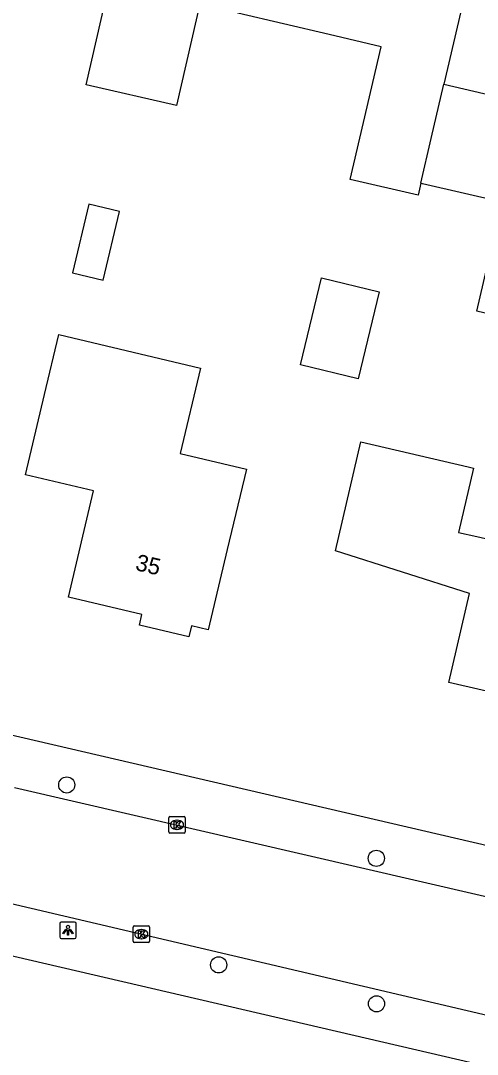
# Model space of a CAD drawing. Extents: x 162186 to 163152, y 385513 to 386513.
# Drawn here: x 162714.9 to 162742.5, y 385892.3 to 385954.9 of the extents above; entities that cross this region are included whole.
import ezdxf

# ---------------------------------------------------------------- set-up
doc = ezdxf.new("R2010")
doc.units = 0
for name, color, linetype in [('IMGEO_Boom', 7, 'Continuous'), ('IMGEO_Kolk', 7, 'Continuous'), ('IMGEO_Lichtpunt', 7, 'Continuous'), ('IMGEO_Pand', 7, 'Continuous'), ('IMGEO_Pand_nummerreeks', 7, 'Continuous'), ('IMGEO_Rijbaan_lokaal_open', 7, 'Continuous'), ('IMGEO_Voetpad_open', 7, 'Continuous')]:
    doc.layers.add(name, color=color, linetype=linetype)

msp = doc.modelspace()

# ---------------------------------------------------------------- linework, layer by layer
at = {"layer": 'IMGEO_Boom'}
for centre in [(162717.658, 385908.645), (162736.394, 385904.2), (162726.851, 385897.749), (162736.406, 385895.394)]:
    msp.add_circle(centre, 0.489, dxfattribs=at)
at = {"layer": 'IMGEO_Kolk'}
for p, q in [((162723.829, 385905.805), (162723.829, 385906.657)), ((162723.904, 385906.731), (162724.756, 385906.731)), ((162724.317, 385906.511), (162724.342, 385906.511)), ((162724.83, 385906.657), (162724.83, 385905.805)), ((162724.756, 385905.731), (162723.904, 385905.731)), ((162724.34, 385905.951), (162724.315, 385905.951)), ((162721.672, 385899.185), (162721.672, 385900.037)), ((162721.747, 385900.111), (162722.599, 385900.111)), ((162722.673, 385900.037), (162722.673, 385899.185)), ((162722.16, 385899.891), (162722.185, 385899.891)), ((162722.599, 385899.111), (162721.747, 385899.111)), ((162722.183, 385899.331), (162722.158, 385899.331))]:
    msp.add_line(p, q, dxfattribs=at)
for points in [[(162723.829, 385905.805), (162723.829, 385906.657)], [(162723.904, 385906.731), (162724.756, 385906.731)], [(162724.15, 385906.431), (162724.273, 385906.431), (162724.273, 385906.28), (162724.403, 385906.431), (162724.567, 385906.431), (162724.421, 385906.28), (162724.574, 385906.031), (162724.422, 385906.031), (162724.337, 385906.195), (162724.273, 385906.128), (162724.273, 385906.031), (162724.15, 385906.031), (162724.15, 385906.431)], [(162724.83, 385906.657), (162724.83, 385905.805)], [(162724.756, 385905.731), (162723.904, 385905.731)], [(162721.672, 385899.185), (162721.672, 385900.037)], [(162721.747, 385900.111), (162722.599, 385900.111)], [(162722.673, 385900.037), (162722.673, 385899.185)], [(162721.993, 385899.811), (162722.116, 385899.811), (162722.116, 385899.66), (162722.246, 385899.811), (162722.41, 385899.811), (162722.264, 385899.66), (162722.417, 385899.411), (162722.265, 385899.411), (162722.18, 385899.575), (162722.116, 385899.508), (162722.116, 385899.411), (162721.993, 385899.411), (162721.993, 385899.811)], [(162722.599, 385899.111), (162721.747, 385899.111)]]:
    msp.add_lwpolyline(points, dxfattribs=at)
for centre, start, end in [((162723.906, 385906.655), 91.55205, 178.44795), ((162723.906, 385906.655), 91.55205, 178.44795), ((162724.754, 385906.655), 1.55205, 88.44795), ((162724.754, 385906.655), 1.55205, 88.44795), ((162723.906, 385905.807), 181.55205, 268.44795), ((162723.906, 385905.807), 181.55205, 268.44795), ((162724.754, 385905.807), 271.55205, 358.44795), ((162724.754, 385905.807), 271.55205, 358.44795), ((162721.749, 385900.035), 91.55205, 178.44795), ((162721.749, 385900.035), 91.55205, 178.44795), ((162722.597, 385900.035), 1.55205, 88.44795), ((162722.597, 385900.035), 1.55205, 88.44795), ((162721.749, 385899.187), 181.55205, 268.44795), ((162721.749, 385899.187), 181.55205, 268.44795), ((162722.597, 385899.187), 271.55205, 358.44795), ((162722.597, 385899.187), 271.55205, 358.44795)]:
    msp.add_arc(centre, 0.0765, start, end, dxfattribs=at)
for centre, major_axis, ratio, start_param, end_param in [((162724.316, 385906.231), (-0.387, 0.002), 0.722429, 4.712389, 7.853982), ((162724.341, 385906.231), (-0.39, 0.002), 0.717154, 1.570796, 4.712389), ((162722.159, 385899.611), (-0.387, 0.002), 0.722429, 4.712389, 7.853982), ((162722.184, 385899.611), (-0.39, 0.002), 0.717154, 1.570796, 4.712389)]:
    msp.add_ellipse(centre, major_axis=major_axis, ratio=ratio, start_param=start_param, end_param=end_param, dxfattribs=at)
at = {"layer": 'IMGEO_Lichtpunt'}
for p, q in [((162717.234, 385900.249), (162717.234, 385899.442)), ((162717.234, 385900.249), (162717.234, 385899.442)), ((162718.136, 385900.344), (162717.328, 385900.344)), ((162718.136, 385900.344), (162717.328, 385900.344)), ((162718.23, 385899.442), (162718.23, 385900.249)), ((162718.23, 385899.442), (162718.23, 385900.249)), ((162717.328, 385899.348), (162718.136, 385899.348)), ((162717.328, 385899.348), (162718.136, 385899.348))]:
    msp.add_line(p, q, dxfattribs=at)
for points in [[(162717.608, 385899.913), (162717.647, 385899.885), (162717.459, 385899.623), (162717.421, 385899.65), (162717.608, 385899.913)], [(162717.71, 385899.865), (162717.757, 385899.865), (162717.757, 385899.543), (162717.71, 385899.543), (162717.71, 385899.865)], [(162717.82, 385899.885), (162717.858, 385899.912), (162718.045, 385899.65), (162718.006, 385899.622), (162717.82, 385899.885)]]:
    msp.add_lwpolyline(points, dxfattribs=at)
msp.add_circle((162717.733, 385900.047), 0.0994, dxfattribs=at)
for centre, start, end in [((162717.328, 385900.249), 90, 180), ((162717.328, 385900.249), 90, 180), ((162718.136, 385900.249), 0, 90), ((162718.136, 385900.249), 0, 90), ((162717.328, 385899.442), 180, 270), ((162717.328, 385899.442), 180, 270), ((162718.136, 385899.442), 270, 0), ((162718.136, 385899.442), 270, 360)]:
    msp.add_arc(centre, 0.0946, start, end, dxfattribs=at)
at = {"layer": 'IMGEO_Pand'}
for points in [[(162710.429, 385963.844), (162711.409, 385968.122), (162712.525, 385972.995), (162723.764, 385970.421), (162723.08, 385967.436), (162728.081, 385966.291), (162726.965, 385961.418), (162724.3, 385949.784), (162718.826, 385951.037), (162720.076, 385956.496), (162716.818, 385957.242), (162717.936, 385962.125), (162710.429, 385963.844)], [(162739.083, 385945.073), (162738.915, 385944.35), (162734.815, 385945.303), (162735.615, 385948.744), (162736.683, 385953.34), (162733.539, 385954.078), (162728.021, 385955.374), (162728.897, 385959.103), (162730.143, 385958.81), (162730.403, 385959.915), (162731.546, 385964.782), (162730.747, 385964.968), (162730.937, 385965.787), (162731.101, 385965.749), (162731.865, 385969.034), (162736.847, 385967.875), (162736.729, 385967.37), (162739.924, 385966.627), (162738.351, 385959.864), (162742.304, 385958.944), (162740.473, 385951.068)], [(162739.083, 385945.073), (162739.713, 385947.791), (162740.473, 385951.068)], [(162740.473, 385951.068), (162749.906, 385948.874)], [(162749.906, 385948.874), (162749.816, 385948.488), (162748.79, 385948.726), (162747.941, 385945.076), (162752.108, 385944.107), (162751.898, 385943.202), (162759.41, 385941.455), (162757.355, 385932.617), (162755.607, 385933.023), (162755.375, 385932.023), (162754.629, 385932.197), (162754.873, 385933.246), (162750.003, 385934.379), (162746.742, 385935.137), (162746.79, 385935.343), (162747.006, 385936.27), (162742.479, 385937.323), (162744.014, 385943.927), (162739.184, 385945.05), (162739.083, 385945.073)], [(162717.997, 385939.653), (162719.856, 385939.211), (162720.846, 385943.374), (162718.988, 385943.816), (162717.997, 385939.653)], [(162736.565, 385938.494), (162735.284, 385933.23), (162731.798, 385934.079), (162733.079, 385939.342), (162736.565, 385938.494)], [(162717.176, 385935.927), (162725.752, 385933.886), (162724.522, 385928.715), (162728.532, 385927.76), (162727.374, 385922.894), (162726.216, 385918.029), (162725.209, 385918.269), (162725.051, 385917.607), (162722.053, 385918.32), (162722.205, 385918.956), (162717.754, 385920.016), (162719.284, 385926.446), (162715.154, 385927.429), (162716.312, 385932.294), (162717.176, 385935.927)], [(162735.446, 385929.41), (162741.942, 385927.905), (162742.278, 385927.827), (162741.375, 385923.931), (162742.469, 385923.678), (162752.641, 385921.321), (162750.615, 385912.579), (162740.788, 385914.856), (162742.035, 385920.237), (162733.921, 385922.827), (162735.446, 385929.41)]]:
    msp.add_lwpolyline(points, dxfattribs=at)
at = {"layer": 'IMGEO_Rijbaan_lokaal_open'}
for points in [[(162714.497, 385908.493), (162746.173, 385901.16), (162746.398, 385901.109)], [(162744.853, 385894.278), (162743.872, 385894.504), (162713.499, 385901.637)]]:
    msp.add_lwpolyline(points, dxfattribs=at)
at = {"layer": 'IMGEO_Voetpad_open'}
for points in [[(162750.77, 385903.177), (162747.115, 385904.027), (162535.867, 385953.127)], [(162532.931, 385940.487), (162533.141, 385940.448), (162742.31, 385891.809)]]:
    msp.add_lwpolyline(points, dxfattribs=at)

# ---------------------------------------------------------------- texts
at = {"layer": 'IMGEO_Pand_nummerreeks'}
msp.add_text('35', height=1, rotation=346.78552, dxfattribs=at).set_placement((162721.757, 385921.665))

doc.saveas('drawing.dxf')
